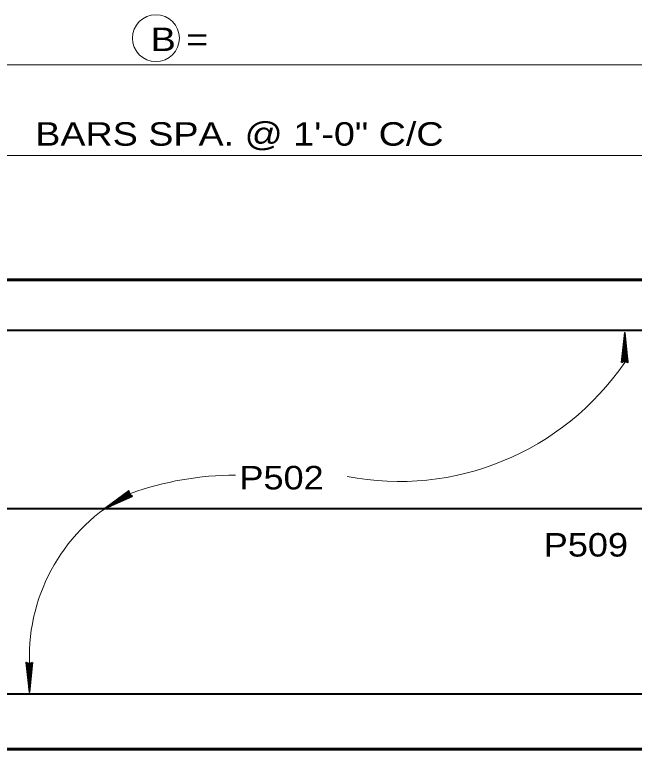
# Model space of a CAD drawing. Extents: x 6.34 to 9.53, y -1.46 to 0.53.
# Drawn here: x 6.9057 to 7.1258, y 0.0454 to 0.3062 of the extents above; entities that cross this region are included whole.
import ezdxf

# ---------------------------------------------------------------- set-up
doc = ezdxf.new("R2010")
doc.units = 0
doc.header["$LTSCALE"] = 0.0033
doc.layers.add('1', color=7, linetype='Continuous', lineweight=40)

msp = doc.modelspace()

# ---------------------------------------------------------------- linework, layer by layer
at = {"layer": '1', "lineweight": 13}
for p, q in [((6.718833, 0.288417), (7.301167, 0.288417)), ((6.735583, 0.256167), (7.2825, 0.256167))]:
    msp.add_line(p, q, dxfattribs=at)
at = {"layer": '1', "lineweight": 60}
msp.add_line((6.718917, 0.212083), (7.30225, 0.212083), dxfattribs=at)
at = {"layer": '1', "lineweight": 35}
for p, q in [((7.122333, 0.18275), (7.122333, 0.193333)), ((7.121333, 0.183), (7.12225, 0.190833)), ((7.121333, 0.183), (7.12225, 0.190833)), ((7.121417, 0.183), (7.12225, 0.190833)), ((7.1215, 0.183), (7.122333, 0.190833)), ((7.1215, 0.183), (7.1225, 0.190833)), ((7.123, 0.182917), (7.12225, 0.19025)), ((7.123167, 0.183), (7.122333, 0.190333)), ((7.12325, 0.183), (7.1225, 0.190333)), ((7.123417, 0.183), (7.122583, 0.190333)), ((6.946833, 0.13625), (6.93775, 0.130917)), ((6.946167, 0.136917), (6.940167, 0.1325)), ((6.946083, 0.136917), (6.94025, 0.132667)), ((6.946333, 0.136917), (6.940417, 0.132417)), ((6.9465, 0.136667), (6.940417, 0.132417)), ((6.947, 0.1355), (6.939833, 0.132083)), ((6.947, 0.1355), (6.939833, 0.132333)), ((6.947083, 0.135417), (6.939833, 0.132083)), ((6.94725, 0.135167), (6.939833, 0.132083)), ((6.94725, 0.135167), (6.939833, 0.132083)), ((6.909833, 0.076), (6.910667, 0.068667)), ((6.91, 0.076), (6.91075, 0.068667)), ((6.910083, 0.076), (6.910917, 0.068667)), ((6.91025, 0.076083), (6.911, 0.06875)), ((6.91175, 0.076), (6.91075, 0.068167)), ((6.910917, 0.07625), (6.910917, 0.065667)), ((6.91175, 0.076), (6.910917, 0.068167)), ((6.911917, 0.076), (6.911, 0.068167)), ((6.911917, 0.076), (6.911, 0.068167)), ((6.911833, 0.076), (6.911, 0.068167))]:
    msp.add_line(p, q, dxfattribs=at)
at = {"layer": '1', "lineweight": 60}
msp.add_lwpolyline([(7.30225, 0.212083), (7.30225, 0.045417), (6.718917, 0.045417), (6.718917, 0.212083)], dxfattribs=at)
at = {"layer": '1'}
for points in [[(6.788333, 0.19), (6.795583, 0.194167), (7.16075, 0.194167)], [(6.73925, 0.130833), (7.159583, 0.130833), (7.280917, 0.130833)], [(6.74, 0.06925), (6.7875, 0.06925), (6.79475, 0.065083), (7.168917, 0.065083)]]:
    msp.add_lwpolyline(points, dxfattribs=at)
at = {"layer": '1', "lineweight": 35}
for points in [[(7.12125, 0.18275), (7.122333, 0.193333), (7.1235, 0.18275), (7.122333, 0.183333)], [(7.12225, 0.1835), (7.122167, 0.188167), (7.12225, 0.188167), (7.12225, 0.18725), (7.122167, 0.1835), (7.122083, 0.1865), (7.122, 0.183333), (7.121917, 0.185583), (7.121833, 0.183333), (7.122083, 0.186833), (7.12225, 0.1915), (7.1225, 0.190583), (7.1225, 0.191833), (7.1225, 0.1835), (7.122667, 0.185917), (7.122667, 0.183333), (7.12225, 0.188667), (7.122917, 0.183333)], [(6.9475, 0.13525), (6.93775, 0.130917), (6.946167, 0.137167), (6.946417, 0.135833)], [(6.946333, 0.135667), (6.94225, 0.133333), (6.942167, 0.133333), (6.943083, 0.133833), (6.94625, 0.135583), (6.94375, 0.134083), (6.946417, 0.135583), (6.944583, 0.134333), (6.946667, 0.135333), (6.9435, 0.134), (6.939417, 0.131583), (6.94, 0.132417), (6.938917, 0.131833), (6.946167, 0.136), (6.944, 0.134833), (6.946167, 0.13625), (6.941833, 0.133167), (6.946083, 0.136417)], [(6.912, 0.07625), (6.910917, 0.065667), (6.90975, 0.07625), (6.910917, 0.075667)], [(6.911, 0.0755), (6.911083, 0.070833), (6.911, 0.070833), (6.911, 0.07175), (6.911083, 0.0755), (6.911167, 0.0725), (6.91125, 0.075667), (6.911333, 0.073417), (6.911417, 0.075667), (6.911167, 0.072167), (6.911, 0.0675), (6.91075, 0.068417), (6.91075, 0.067167), (6.91075, 0.0755), (6.910583, 0.073083), (6.910583, 0.075667), (6.911, 0.070333), (6.910333, 0.075667)]]:
    msp.add_lwpolyline(points, close=True, dxfattribs=at)
for points in [[(7.12225, 0.1835), (7.1215, 0.183083), (7.12175, 0.183333), (7.122083, 0.1835), (7.122, 0.18375), (7.121667, 0.183583), (7.122417, 0.183417), (7.122917, 0.18325), (7.123333, 0.183)], [(6.946333, 0.135667), (6.947, 0.1355), (6.946583, 0.135417), (6.946333, 0.1355), (6.946167, 0.135333), (6.9465, 0.135167), (6.94625, 0.136), (6.946083, 0.1365), (6.946083, 0.136917)], [(6.911, 0.0755), (6.91175, 0.075917), (6.9115, 0.075667), (6.911167, 0.0755), (6.91125, 0.07525), (6.911583, 0.075417), (6.910833, 0.075583), (6.910333, 0.07575), (6.909917, 0.076)]]:
    msp.add_lwpolyline(points, dxfattribs=at)
at = {"layer": '1', "lineweight": 13}
msp.add_circle((6.955833, 0.297833), 0.008333, dxfattribs=at)
for centre, radius, start, end in [((7.042221, 0.237522), 0.097046, 259.02789, 325.63978), ((6.984343, 0.031275), 0.111475, 90.13359, 109.66293), ((6.976028, 0.078181), 0.06514, 118.005, 181.69858)]:
    msp.add_arc(centre, radius, start, end, dxfattribs=at)

# ---------------------------------------------------------------- texts
at = {"layer": '1'}
for s, width, p in [('B =      ', 1.2, (6.954, 0.29325)), ('BARS SPA. @ 1\'-0" C/C', 1.2, (6.913, 0.259667)), ('P502', 1.15, (6.9855, 0.137667)), ('P509', 1.15, (7.093583, 0.113833))]:
    msp.add_text(s, height=0.008334, dxfattribs=dict(at, width=width)).set_placement(p)

doc.saveas('drawing.dxf')
